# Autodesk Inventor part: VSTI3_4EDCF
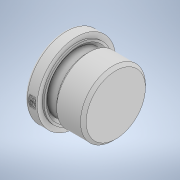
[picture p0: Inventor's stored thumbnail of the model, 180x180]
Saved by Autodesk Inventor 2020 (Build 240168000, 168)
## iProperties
Created: 2019-12
Part Number: VSTI3_4EDCF
Material: Generico
Description: STEP AP203
Document SubType Name: Modeling
Designer: carlo
Density: 1 g/cm^3
Appearance: Default
DataBaseUnit: MM
Sending System: PARTsolutions
Title: p:/temp/worker_145/temp/exporttempdir_1976_396_7PJDV/format_0/EO Verschluss-Stopfen fuer Einschraubloecher VSTI3_4EDCF.stp
Revision Number: NONE
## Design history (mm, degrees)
feature "_EO Verschluss-Stopfen fuer Einschraubloecher VSTI3_4EDCF"
node "Piano di lavoro1"
node "Piano di lavoro2"
node "Asse di lavoro1"
node "Solido1"
other parameters: "d0" = 0, "d1" = 0
